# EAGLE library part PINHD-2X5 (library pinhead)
PIN HEADER
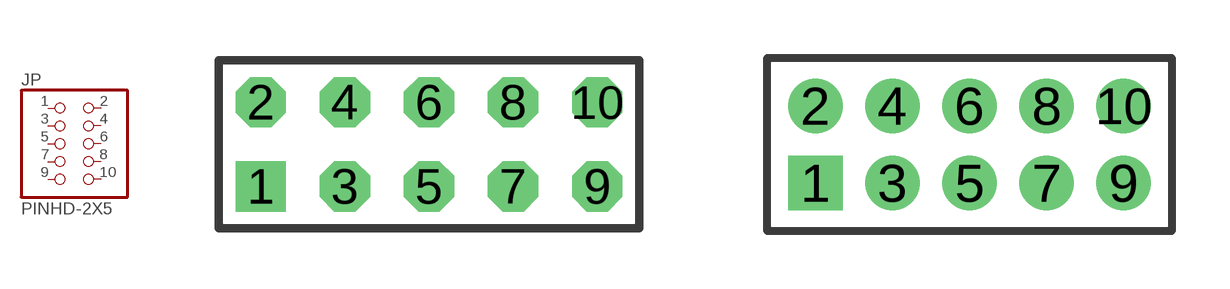
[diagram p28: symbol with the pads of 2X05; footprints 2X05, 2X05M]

Designator prefix JP

## PINHD-2X5  [2X05]
1  1  pas
2  2  pas
3  3  pas
4  4  pas
5  5  pas
6  6  pas
7  7  pas
8  8  pas
9  9  pas
10  10  pas

## PINHD-2X5M  [2X05M]
Pads as for 2X05

## Footprint 2X05 (pad centres in mm)
PIN HEADER - 0.1"
drill 1.016 square: 1 -5.08,-1.27
drill 1.016 octagon: 2 -5.08,1.27; 3 -2.54,-1.27; 4 -2.54,1.27; 5 0,-1.27; 6 0,1.27; 7 2.54,-1.27; 8 2.54,1.27; 9 5.08,-1.27; 10 5.08,1.27

## Footprint 2X05M (pad centres in mm)
PIN HEADER - 2MM"
drill 0.914 square: 1 -4,-1
drill 0.914 round: 2 -4,1; 3 -2,-1; 4 -2,1; 5 0,-1; 6 0,1; 7 2,-1; 8 2,1; 9 4,-1; 10 4,1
